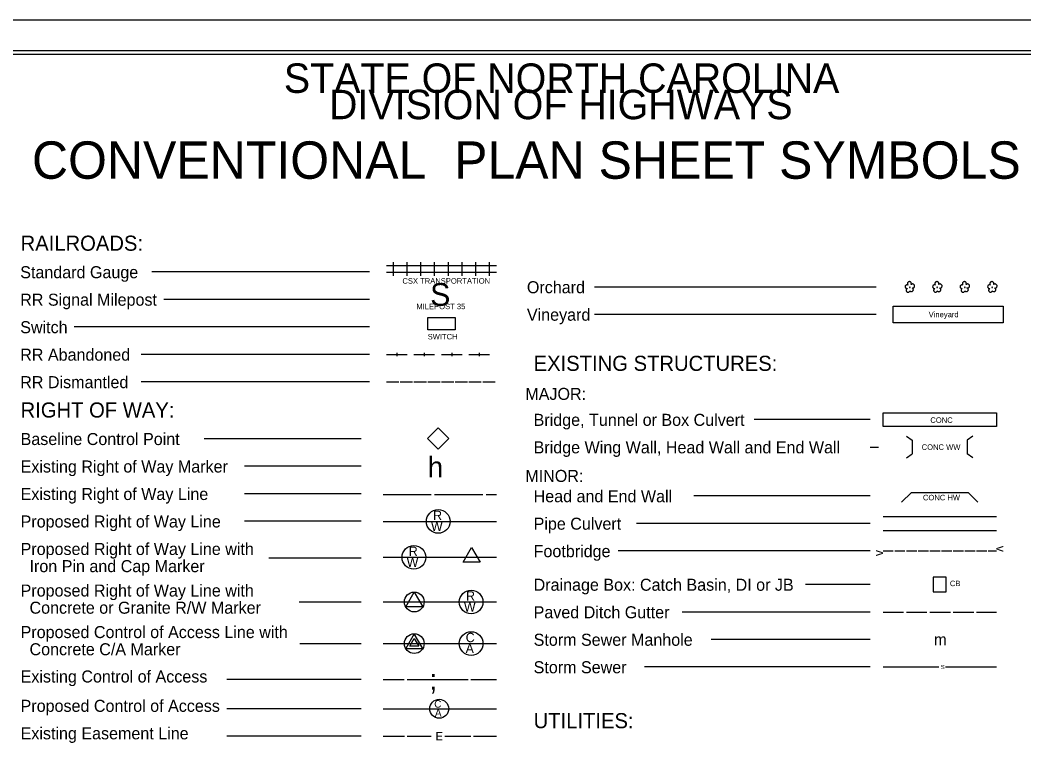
# Model space of a CAD drawing. Extents: x 573687 to 575553, y -54556 to -52223.
# Drawn here: x 574249 to 574979, y -53982 to -53456 of the extents above; entities that cross this region are included whole.
import ezdxf

# ---------------------------------------------------------------- set-up
doc = ezdxf.new("R2010")
doc.units = 0
for name, color, linetype in [('Prop Dimension', 7, 'Continuous'), ('Sheet Cutting Line CELL', 7, 'Continuous'), ('Sheet Plot Border Inside CELL', 7, 'Continuous'), ('Sheet Plot Border Outside CELL', 7, 'Continuous'), ('Sheet Symbology CELL', 7, 'Continuous')]:
    doc.layers.add(name, color=color, linetype=linetype)

msp = doc.modelspace()

# ---------------------------------------------------------------- linework, layer by layer
at = {"layer": 'Prop Dimension'}
msp.add_lwpolyline([(574545.27, -53759.95), (574553.09, -53752.13), (574560.91, -53759.95), (574553.09, -53767.77)], close=True, dxfattribs=at)
at = {"layer": 'Sheet Cutting Line CELL'}
msp.add_line((575371.45, -53455.5), (573687.45, -53455.5), dxfattribs=at)
at = {"layer": 'Sheet Plot Border Inside CELL'}
msp.add_lwpolyline([(573700.45, -54533.05), (575366.95, -54533.05), (575366.95, -53477.95), (573700.45, -53477.95)], close=True, dxfattribs=at)
at = {"layer": 'Sheet Plot Border Outside CELL'}
msp.add_lwpolyline([(573687.45, -54555.5), (575371.45, -54555.5), (575371.45, -53455.5), (573687.45, -53455.5)], close=True, dxfattribs=at)
at = {"layer": 'Sheet Symbology CELL'}
for p, q in [((574515.44, -53634.03), (574525.44, -53634.03)), ((574520.44, -53641.53), (574520.44, -53631.53)), ((574525.44, -53634.03), (574535.44, -53634.03)), ((574530.44, -53641.53), (574530.44, -53631.53)), ((574535.44, -53634.03), (574545.44, -53634.03)), ((574540.44, -53641.53), (574540.44, -53631.53)), ((574545.44, -53634.03), (574555.44, -53634.03)), ((574550.44, -53641.53), (574550.44, -53631.53)), ((574555.44, -53634.03), (574565.44, -53634.03)), ((574560.44, -53641.53), (574560.44, -53631.53)), ((574565.44, -53634.03), (574575.44, -53634.03)), ((574570.44, -53641.53), (574570.44, -53631.53)), ((574575.44, -53634.03), (574585.44, -53634.03)), ((574580.44, -53641.53), (574580.44, -53631.53)), ((574585.44, -53634.03), (574595.44, -53634.03)), ((574590.44, -53641.53), (574590.44, -53631.53)), ((574503.05, -53638.79), (574344.64, -53638.79)), ((574515.44, -53639.03), (574525.44, -53639.03)), ((574525.44, -53639.03), (574535.44, -53639.03)), ((574535.44, -53639.03), (574545.44, -53639.03)), ((574545.44, -53639.03), (574555.44, -53639.03)), ((574555.44, -53639.03), (574565.44, -53639.03)), ((574565.44, -53639.03), (574575.44, -53639.03)), ((574575.44, -53639.03), (574585.44, -53639.03)), ((574585.44, -53639.03), (574595.44, -53639.03)), ((574871.77, -53649.72), (574666.84, -53649.72)), ((574503.05, -53658.79), (574353.5, -53658.79)), ((574871.77, -53669.72), (574666.84, -53669.72)), ((574503.05, -53678.79), (574288.14, -53678.79)), ((574503.05, -53698.79), (574336.89, -53698.79)), ((574515.44, -53698.79), (574530.44, -53698.79)), ((574522.94, -53697.54), (574522.94, -53700.04)), ((574535.44, -53698.79), (574550.44, -53698.79)), ((574542.94, -53697.54), (574542.94, -53700.04)), ((574555.44, -53698.79), (574570.44, -53698.79)), ((574562.94, -53697.54), (574562.94, -53700.04)), ((574575.44, -53698.79), (574590.44, -53698.79)), ((574582.94, -53697.54), (574582.94, -53700.04)), ((574503.05, -53718.79), (574336.89, -53718.79)), ((574503.05, -53718.79), (574336.89, -53718.79)), ((574515.44, -53718.79), (574524.44, -53718.79)), ((574525.44, -53718.79), (574534.44, -53718.79)), ((574535.44, -53718.79), (574544.44, -53718.79)), ((574545.44, -53718.79), (574554.44, -53718.79)), ((574555.44, -53718.79), (574564.44, -53718.79)), ((574565.44, -53718.79), (574574.44, -53718.79)), ((574575.44, -53718.79), (574584.44, -53718.79)), ((574585.44, -53718.79), (574594.44, -53718.79)), ((574867.46, -53746.19), (574783.03, -53746.19)), ((574893.91, -53758.32), (574898.01, -53761.19)), ((574942.11, -53758.32), (574938.01, -53761.19)), ((574496.91, -53760.14), (574382.7, -53760.14)), ((574867.46, -53766.19), (574873.45, -53766.19)), ((574898.01, -53761.19), (574898.01, -53771.19)), ((574938.01, -53761.19), (574938.01, -53771.19)), ((574893.91, -53774.05), (574898.01, -53771.19)), ((574942.11, -53774.05), (574938.01, -53771.19)), ((574496.91, -53780.14), (574411.98, -53780.14)), ((574496.91, -53800.14), (574411.98, -53800.14)), ((574512.94, -53800.72), (574547.94, -53800.72)), ((574550.44, -53800.72), (574585.44, -53800.72)), ((574587.94, -53800.72), (574595.44, -53800.72)), ((574867.46, -53801.76), (574739.16, -53801.76)), ((574890.31, -53806.33), (574897.38, -53799.26)), ((574897.38, -53799.26), (574938.63, -53799.26)), ((574938.63, -53799.26), (574945.71, -53806.33)), ((574876.76, -53816.76), (574959.26, -53816.76)), ((574496.91, -53820.14), (574411.98, -53820.14)), ((574512.94, -53820.27), (574595.44, -53820.27)), ((574867.46, -53821.76), (574697.27, -53821.76)), ((574876.76, -53826.76), (574959.26, -53826.76)), ((574512.94, -53846.39), (574595.44, -53846.39)), ((574577.39, -53846.39), (574577.39, -53846.39)), ((574867.46, -53841.76), (574683.98, -53841.76)), ((574876.76, -53841.76), (574884.26, -53841.76)), ((574885.26, -53841.76), (574892.76, -53841.76)), ((574893.76, -53841.76), (574901.26, -53841.76)), ((574902.26, -53841.76), (574909.76, -53841.76)), ((574910.76, -53841.76), (574918.26, -53841.76)), ((574919.26, -53841.76), (574926.76, -53841.76)), ((574927.76, -53841.76), (574935.26, -53841.76)), ((574936.26, -53841.76), (574943.76, -53841.76)), ((574944.76, -53841.76), (574952.26, -53841.76)), ((574953.26, -53841.76), (574959.26, -53841.76)), ((574496.91, -53846.99), (574429.8, -53846.99)), ((574867.46, -53866.19), (574820.26, -53866.19)), ((574496.91, -53879.03), (574451.93, -53879.03)), ((574512.94, -53878.89), (574595.44, -53878.89)), ((574535.64, -53878.89), (574535.64, -53878.89)), ((574867.46, -53886.19), (574730.51, -53886.19)), ((574876.76, -53886.19), (574891.76, -53886.19)), ((574893.76, -53886.19), (574908.76, -53886.19)), ((574910.76, -53886.19), (574925.76, -53886.19)), ((574927.76, -53886.19), (574942.76, -53886.19)), ((574944.76, -53886.19), (574959.26, -53886.19)), ((574496.91, -53909.27), (574452.3, -53909.27)), ((574512.94, -53909.14), (574595.44, -53909.14)), ((574535.64, -53909.14), (574535.64, -53909.14)), ((574867.46, -53906.19), (574751.78, -53906.19)), ((574867.46, -53926.19), (574703.26, -53926.19)), ((574876.76, -53926.19), (574917.28, -53926.19)), ((574922.28, -53926.19), (574959.26, -53926.19)), ((574496.91, -53935.22), (574399.36, -53935.22)), ((574512.94, -53935.22), (574528.41, -53935.22)), ((574530.41, -53935.22), (574574.82, -53935.22)), ((574576.82, -53935.22), (574595.44, -53935.22)), ((574496.91, -53956.57), (574399.36, -53956.57)), ((574512.94, -53956.57), (574595.44, -53956.57)), ((574496.91, -53976.57), (574399.36, -53976.57)), ((574512.94, -53976.57), (574528.46, -53976.57)), ((574530.46, -53976.57), (574547.96, -53976.57)), ((574557.96, -53976.57), (574576.71, -53976.57)), ((574578.71, -53976.57), (574595.44, -53976.57))]:
    msp.add_line(p, q, dxfattribs=at)
for points in [[(575354.45, -53480.5), (573854.45, -53480.5), (573854.45, -54529.49), (575354.45, -54529.49)], [(574545.44, -53671.83), (574565.44, -53671.83), (574565.44, -53680.93), (574545.44, -53680.93)], [(574571.14, -53849.99), (574577.39, -53839.19), (574583.64, -53849.99)], [(574913.2, -53871.5), (574922.81, -53871.5), (574922.81, -53860.86), (574913.2, -53860.86)], [(574529.39, -53882.49), (574535.64, -53871.69), (574541.89, -53882.49)], [(574529.39, -53912.74), (574541.89, -53912.74), (574535.64, -53901.94)], [(574532.38, -53911.02), (574535.64, -53905.37), (574538.91, -53911.02)]]:
    msp.add_lwpolyline(points, close=True, dxfattribs=at)
for points in [[(574897.22, -53647.97), (574897.37, -53647.67), (574897.42, -53647.37), (574897.37, -53647.07), (574897.32, -53646.77), (574897.17, -53646.52), (574897.02, -53646.27), (574896.77, -53646.07), (574896.52, -53645.92), (574896.17, -53645.82), (574895.92, -53645.82), (574895.62, -53645.87), (574895.32, -53645.97), (574895.07, -53646.12), (574894.82, -53646.32), (574894.67, -53646.62), (574894.57, -53646.87), (574894.52, -53647.17), (574894.52, -53647.47), (574894.57, -53647.77), (574894.72, -53648.02), (574894.92, -53648.32), (574894.67, -53648.17), (574894.37, -53648.12), (574894.07, -53648.12), (574893.82, -53648.22), (574893.57, -53648.32), (574893.32, -53648.52), (574893.12, -53648.72), (574892.97, -53648.97), (574892.92, -53649.22), (574892.87, -53649.57), (574892.92, -53649.82), (574893.02, -53650.07), (574893.22, -53650.32), (574893.37, -53650.52), (574893.62, -53650.67), (574893.92, -53650.82), (574894.17, -53650.87), (574894.47, -53650.87), (574894.22, -53650.97), (574893.97, -53651.17), (574893.82, -53651.37), (574893.72, -53651.67), (574893.62, -53651.97), (574893.62, -53652.22), (574893.67, -53652.52), (574893.82, -53652.77), (574893.97, -53653.02), (574894.17, -53653.22), (574894.42, -53653.37), (574894.67, -53653.47), (574894.97, -53653.47), (574895.27, -53653.47), (574895.52, -53653.42), (574895.77, -53653.22), (574896.02, -53653.07), (574896.27, -53652.62)], [(574896.27, -53652.62), (574896.87, -53652.97), (574897.17, -53653.07), (574897.47, -53653.12), (574897.77, -53653.07), (574898.02, -53652.97), (574898.27, -53652.82), (574898.52, -53652.62), (574898.67, -53652.37), (574898.77, -53652.12), (574898.87, -53651.82), (574898.82, -53651.52), (574898.77, -53651.22), (574898.57, -53650.92), (574898.42, -53650.72), (574898.17, -53650.57), (574897.87, -53650.42), (574898.17, -53650.47), (574898.52, -53650.47), (574898.77, -53650.37), (574899.07, -53650.22), (574899.32, -53650.07), (574899.52, -53649.82), (574899.67, -53649.52), (574899.72, -53649.22), (574899.77, -53648.92), (574899.72, -53648.62), (574899.62, -53648.32), (574899.42, -53648.07), (574899.17, -53647.82), (574898.92, -53647.67), (574898.62, -53647.57), (574898.32, -53647.52), (574898.02, -53647.52), (574897.72, -53647.62), (574897.47, -53647.77), (574897.22, -53647.97)], [(574917.22, -53647.97), (574917.37, -53647.67), (574917.42, -53647.37), (574917.37, -53647.07), (574917.32, -53646.77), (574917.17, -53646.52), (574917.02, -53646.27), (574916.77, -53646.07), (574916.52, -53645.92), (574916.17, -53645.82), (574915.92, -53645.82), (574915.62, -53645.87), (574915.32, -53645.97), (574915.07, -53646.12), (574914.82, -53646.32), (574914.67, -53646.62), (574914.57, -53646.87), (574914.52, -53647.17), (574914.52, -53647.47), (574914.57, -53647.77), (574914.72, -53648.02), (574914.92, -53648.32), (574914.67, -53648.17), (574914.37, -53648.12), (574914.07, -53648.12), (574913.82, -53648.22), (574913.57, -53648.32), (574913.32, -53648.52), (574913.12, -53648.72), (574912.97, -53648.97), (574912.92, -53649.22), (574912.87, -53649.57), (574912.92, -53649.82), (574913.02, -53650.07), (574913.22, -53650.32), (574913.37, -53650.52), (574913.62, -53650.67), (574913.92, -53650.82), (574914.17, -53650.87), (574914.47, -53650.87), (574914.22, -53650.97), (574913.97, -53651.17), (574913.82, -53651.37), (574913.72, -53651.67), (574913.62, -53651.97), (574913.62, -53652.22), (574913.67, -53652.52), (574913.82, -53652.77), (574913.97, -53653.02), (574914.17, -53653.22), (574914.42, -53653.37), (574914.67, -53653.47), (574914.97, -53653.47), (574915.27, -53653.47), (574915.52, -53653.42), (574915.77, -53653.22), (574916.02, -53653.07), (574916.27, -53652.62)], [(574916.27, -53652.62), (574916.87, -53652.97), (574917.17, -53653.07), (574917.47, -53653.12), (574917.77, -53653.07), (574918.02, -53652.97), (574918.27, -53652.82), (574918.52, -53652.62), (574918.67, -53652.37), (574918.77, -53652.12), (574918.87, -53651.82), (574918.82, -53651.52), (574918.77, -53651.22), (574918.57, -53650.92), (574918.42, -53650.72), (574918.17, -53650.57), (574917.87, -53650.42), (574918.17, -53650.47), (574918.52, -53650.47), (574918.77, -53650.37), (574919.07, -53650.22), (574919.32, -53650.07), (574919.52, -53649.82), (574919.67, -53649.52), (574919.72, -53649.22), (574919.77, -53648.92), (574919.72, -53648.62), (574919.62, -53648.32), (574919.42, -53648.07), (574919.17, -53647.82), (574918.92, -53647.67), (574918.62, -53647.57), (574918.32, -53647.52), (574918.02, -53647.52), (574917.72, -53647.62), (574917.47, -53647.77), (574917.22, -53647.97)], [(574937.22, -53647.97), (574937.37, -53647.67), (574937.42, -53647.37), (574937.37, -53647.07), (574937.32, -53646.77), (574937.17, -53646.52), (574937.02, -53646.27), (574936.77, -53646.07), (574936.52, -53645.92), (574936.17, -53645.82), (574935.92, -53645.82), (574935.62, -53645.87), (574935.32, -53645.97), (574935.07, -53646.12), (574934.82, -53646.32), (574934.67, -53646.62), (574934.57, -53646.87), (574934.52, -53647.17), (574934.52, -53647.47), (574934.57, -53647.77), (574934.72, -53648.02), (574934.92, -53648.32), (574934.67, -53648.17), (574934.37, -53648.12), (574934.07, -53648.12), (574933.82, -53648.22), (574933.57, -53648.32), (574933.32, -53648.52), (574933.12, -53648.72), (574932.97, -53648.97), (574932.92, -53649.22), (574932.87, -53649.57), (574932.92, -53649.82), (574933.02, -53650.07), (574933.22, -53650.32), (574933.37, -53650.52), (574933.62, -53650.67), (574933.92, -53650.82), (574934.17, -53650.87), (574934.47, -53650.87), (574934.22, -53650.97), (574933.97, -53651.17), (574933.82, -53651.37), (574933.72, -53651.67), (574933.62, -53651.97), (574933.62, -53652.22), (574933.67, -53652.52), (574933.82, -53652.77), (574933.97, -53653.02), (574934.17, -53653.22), (574934.42, -53653.37), (574934.67, -53653.47), (574934.97, -53653.47), (574935.27, -53653.47), (574935.52, -53653.42), (574935.77, -53653.22), (574936.02, -53653.07), (574936.27, -53652.62)], [(574936.27, -53652.62), (574936.87, -53652.97), (574937.17, -53653.07), (574937.47, -53653.12), (574937.77, -53653.07), (574938.02, -53652.97), (574938.27, -53652.82), (574938.52, -53652.62), (574938.67, -53652.37), (574938.77, -53652.12), (574938.87, -53651.82), (574938.82, -53651.52), (574938.77, -53651.22), (574938.57, -53650.92), (574938.42, -53650.72), (574938.17, -53650.57), (574937.87, -53650.42), (574938.17, -53650.47), (574938.52, -53650.47), (574938.77, -53650.37), (574939.07, -53650.22), (574939.32, -53650.07), (574939.52, -53649.82), (574939.67, -53649.52), (574939.72, -53649.22), (574939.77, -53648.92), (574939.72, -53648.62), (574939.62, -53648.32), (574939.42, -53648.07), (574939.17, -53647.82), (574938.92, -53647.67), (574938.62, -53647.57), (574938.32, -53647.52), (574938.02, -53647.52), (574937.72, -53647.62), (574937.47, -53647.77), (574937.22, -53647.97)], [(574957.22, -53647.97), (574957.37, -53647.67), (574957.42, -53647.37), (574957.37, -53647.07), (574957.32, -53646.77), (574957.17, -53646.52), (574957.02, -53646.27), (574956.77, -53646.07), (574956.52, -53645.92), (574956.17, -53645.82), (574955.92, -53645.82), (574955.62, -53645.87), (574955.32, -53645.97), (574955.07, -53646.12), (574954.82, -53646.32), (574954.67, -53646.62), (574954.57, -53646.87), (574954.52, -53647.17), (574954.52, -53647.47), (574954.57, -53647.77), (574954.72, -53648.02), (574954.92, -53648.32), (574954.67, -53648.17), (574954.37, -53648.12), (574954.07, -53648.12), (574953.82, -53648.22), (574953.57, -53648.32), (574953.32, -53648.52), (574953.12, -53648.72), (574952.97, -53648.97), (574952.92, -53649.22), (574952.87, -53649.57), (574952.92, -53649.82), (574953.02, -53650.07), (574953.22, -53650.32), (574953.37, -53650.52), (574953.62, -53650.67), (574953.92, -53650.82), (574954.17, -53650.87), (574954.47, -53650.87), (574954.22, -53650.97), (574953.97, -53651.17), (574953.82, -53651.37), (574953.72, -53651.67), (574953.62, -53651.97), (574953.62, -53652.22), (574953.67, -53652.52), (574953.82, -53652.77), (574953.97, -53653.02), (574954.17, -53653.22), (574954.42, -53653.37), (574954.67, -53653.47), (574954.97, -53653.47), (574955.27, -53653.47), (574955.52, -53653.42), (574955.77, -53653.22), (574956.02, -53653.07), (574956.27, -53652.62)], [(574956.27, -53652.62), (574956.87, -53652.97), (574957.17, -53653.07), (574957.47, -53653.12), (574957.77, -53653.07), (574958.02, -53652.97), (574958.27, -53652.82), (574958.52, -53652.62), (574958.67, -53652.37), (574958.77, -53652.12), (574958.87, -53651.82), (574958.82, -53651.52), (574958.77, -53651.22), (574958.57, -53650.92), (574958.42, -53650.72), (574958.17, -53650.57), (574957.87, -53650.42), (574958.17, -53650.47), (574958.52, -53650.47), (574958.77, -53650.37), (574959.07, -53650.22), (574959.32, -53650.07), (574959.52, -53649.82), (574959.67, -53649.52), (574959.72, -53649.22), (574959.77, -53648.92), (574959.72, -53648.62), (574959.62, -53648.32), (574959.42, -53648.07), (574959.17, -53647.82), (574958.92, -53647.67), (574958.62, -53647.57), (574958.32, -53647.52), (574958.02, -53647.52), (574957.72, -53647.62), (574957.47, -53647.77), (574957.22, -53647.97)], [(574896.37, -53649.72), (574896.22, -53649.72), (574896.12, -53649.77), (574896.02, -53649.82), (574896.02, -53649.97), (574896.02, -53650.07), (574896.12, -53650.17), (574896.27, -53650.17), (574896.37, -53650.17), (574896.47, -53650.07), (574896.52, -53649.92), (574896.47, -53649.82), (574896.37, -53649.72)], [(574916.37, -53649.72), (574916.22, -53649.72), (574916.12, -53649.77), (574916.02, -53649.82), (574916.02, -53649.97), (574916.02, -53650.07), (574916.12, -53650.17), (574916.27, -53650.17), (574916.37, -53650.17), (574916.47, -53650.07), (574916.52, -53649.92), (574916.47, -53649.82), (574916.37, -53649.72)], [(574936.37, -53649.72), (574936.22, -53649.72), (574936.12, -53649.77), (574936.02, -53649.82), (574936.02, -53649.97), (574936.02, -53650.07), (574936.12, -53650.17), (574936.27, -53650.17), (574936.37, -53650.17), (574936.47, -53650.07), (574936.52, -53649.92), (574936.47, -53649.82), (574936.37, -53649.72)], [(574956.37, -53649.72), (574956.22, -53649.72), (574956.12, -53649.77), (574956.02, -53649.82), (574956.02, -53649.97), (574956.02, -53650.07), (574956.12, -53650.17), (574956.27, -53650.17), (574956.37, -53650.17), (574956.47, -53650.07), (574956.52, -53649.92), (574956.47, -53649.82), (574956.37, -53649.72)], [(574884.17, -53663.72), (574964.17, -53663.72), (574964.17, -53675.72), (574884.17, -53675.72), (574884.17, -53663.72)], [(574876.76, -53741.19), (574959.26, -53741.19), (574959.26, -53751.19), (574876.76, -53751.19), (574876.76, -53741.19)]]:
    msp.add_lwpolyline(points, dxfattribs=at)
for centre, radius in [((574553.06, -53820.27), 8.61), ((574535.36, -53846.39), 8.61), ((574535.64, -53878.89), 7.2), ((574577.04, -53878.89), 8.61), ((574535.64, -53909.14), 7.2), ((574577.04, -53909.14), 8.61), ((574553.82, -53956.57), 6.89)]:
    msp.add_circle(centre, radius, dxfattribs=at)

# ---------------------------------------------------------------- texts
for s, height, p in [('STATE OF NORTH CAROLINA', 21.419, (574440.75, -53508.46)), ('DIVISION OF HIGHWAYS', 21.419, (574473.59, -53527.63)), ('CONVENTIONAL  PLAN SHEET SYMBOLS', 27.2003, (574257.43, -53570.96)), ('RAILROADS:', 11, (574249.16, -53623.34)), ('Standard Gauge', 8.75, (574248.89, -53643.32)), ('S', 16.5, (574547.21, -53663.42)), ('Orchard', 8.75, (574617.61, -53654.25)), ('RR Signal Milepost', 8.75, (574248.89, -53663.32)), ('Vineyard', 8.75, (574617.61, -53674.25)), ('Switch', 8.75, (574248.89, -53683.32)), ('RR Abandoned', 8.75, (574248.89, -53703.32)), ('EXISTING STRUCTURES:', 11, (574622.5, -53710.74)), ('RR Dismantled', 8.75, (574248.89, -53723.32)), ('MAJOR:', 8.75, (574616.47, -53731.85)), ('RIGHT OF WAY:', 11, (574249.16, -53744.69)), ('Bridge, Tunnel or Box Culvert', 8.75, (574622.5, -53750.74)), ('CONC', 4, (574911.2, -53748.55)), ('Baseline Control Point', 8.75, (574249.16, -53764.69)), ('Bridge Wing Wall, Head Wall and End Wall', 8.75, (574622.5, -53770.74)), ('h', 15, (574545.46, -53788.22)), ('Existing Right of Way Marker', 8.75, (574249.16, -53784.69)), ('MINOR:', 8.75, (574616.47, -53791.55)), ('Existing Right of Way Line', 8.75, (574249.16, -53804.69)), ('Head and End Wall', 8.75, (574622.5, -53806.31)), ('Proposed Right of Way Line', 8.75, (574249.16, -53824.69)), ('R', 6.75, (574549.36, -53819.25)), ('Pipe Culvert', 8.75, (574622.5, -53826.29)), ('W', 6.75, (574547.82, -53827.2)), ('Proposed Right of Way Line with', 8.75, (574249.16, -53844.69)), ('R', 6.75, (574531.66, -53845.38)), ('Footbridge', 8.75, (574622.51, -53846.29)), ('W', 6.75, (574530.12, -53853.33)), ('  Iron Pin and Cap Marker', 8.75, (574249.16, -53857.19)), ('Proposed Right of Way Line with', 8.75, (574249.16, -53874.92)), ('Drainage Box: Catch Basin, DI or JB', 8.75, (574622.51, -53870.72)), ('R', 6.75, (574573.33, -53877.88)), ('  Concrete or Granite R/W Marker', 8.75, (574249.16, -53887.42)), ('W', 6.75, (574571.79, -53885.83)), ('Paved Ditch Gutter', 8.75, (574622.51, -53890.74)), ('Proposed Control of Access Line with', 8.75, (574249.16, -53905.16)), ('C', 6.75, (574573.08, -53908.12)), ('Storm Sewer Manhole', 8.75, (574622.51, -53910.74)), ('m', 8.25, (574913.88, -53910.31)), ('  Concrete C/A Marker', 8.75, (574249.16, -53917.66)), ('A', 6.75, (574573.02, -53916.07)), ('Storm Sewer', 8.75, (574622.51, -53930.74)), ('S', 3, (574918.88, -53927.69)), ('Existing Control of Access', 8.75, (574249.16, -53937.48)), (';', 15, (574546.69, -53942.72)), ('Proposed Control of Access', 8.75, (574249.16, -53958.83)), ('C', 5.4, (574550.16, -53955.76)), ('A', 5.4, (574550.69, -53962.24)), ('UTILITIES:', 11, (574622.5, -53970.74)), ('Existing Easement Line', 8.75, (574249.16, -53978.83)), ('E', 6, (574551.16, -53979.57))]:
    msp.add_text(s, height=height, dxfattribs=at).set_placement(p)
for s, height, rotation, p in [('CSX TRANSPORTATION', 4, 360, (574527.01, -53647.27)), ('MILEPOST 35', 4, 360, (574537.19, -53665.84)), ('Vineyard', 4, 0.00002, (574909.99, -53671.72)), ('SWITCH', 4, 360, (574545.39, -53687.84)), ('CONC WW', 4, 0.00002, (574904.88, -53768.19)), ('CONC HW', 4, 360, (574905.81, -53804.92)), ('v', 6.6, 270.24085, (574959.25, -53838.02)), ('v', 6.6, 89.75915, (574876.75, -53845.49)), ('CB', 4, 360, (574925.45, -53867.36))]:
    msp.add_text(s, height=height, rotation=rotation, dxfattribs=at).set_placement(p)

doc.saveas('drawing.dxf')
